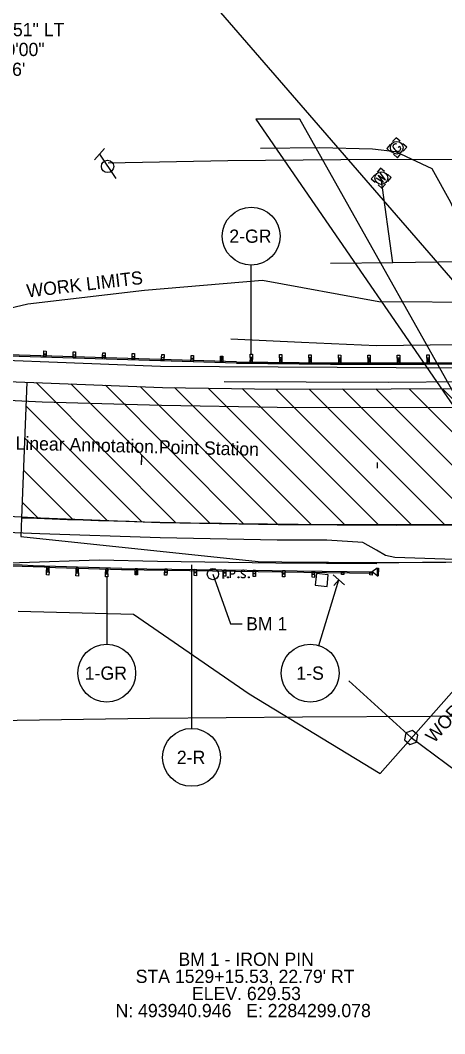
# Model space of a CAD drawing. Extents: x 0 to 1424, y 0 to 866.
# Drawn here: x 892.6 to 982.6, y 543.7 to 758.3 of the extents above; entities that cross this region are included whole.
import ezdxf

# ---------------------------------------------------------------- set-up
doc = ezdxf.new("R2010")
doc.units = 0
for name, color, linetype in [('BR_X_Sub_Backwall', 7, 'Continuous'), ('DR_P_Erosion_Control', 7, 'Continuous'), ('DR_X_Culvert', 7, 'Continuous'), ('DT_P_Slope_Break_Line', 7, 'Continuous'), ('GE_P_Alignment', 7, 'Continuous'), ('GE_P_Alignment_100_Bearings', 7, 'Continuous'), ('GE_P_Alignment_100_Distances', 7, 'Continuous'), ('GE_X_Alignment', 7, 'Continuous'), ('GE_X_Alignment_100_Stations', 7, 'Continuous'), ('GE_X_Alignment_500_Stations', 7, 'Continuous'), ('HY_P_Water_Edge', 7, 'Continuous'), ('HY_X_Water_Edge', 7, 'Continuous'), ('MT_P_Cells', 7, 'Continuous'), ('MT_P_Channelizing_Line', 7, 'Continuous'), ('MT_P_Edge_Line', 7, 'Continuous'), ('MT_P_Temp_Road', 7, 'Continuous'), ('PV_P_Drive', 7, 'Continuous'), ('PV_P_EOP', 7, 'Continuous'), ('PV_P_Shoulder', 7, 'Continuous'), ('RD_P_GR_Lt', 7, 'Continuous'), ('RD_P_GR_Rt', 7, 'Continuous'), ('TX_P_1', 7, 'Continuous'), ('TX_X_1', 7, 'Continuous'), ('XS_P_Pavt_Surface', 7, 'Continuous')]:
    doc.layers.add(name, color=color, linetype=linetype)

msp = doc.modelspace()

# ---------------------------------------------------------------- linework, layer by layer
at = {"layer": 'BR_X_Sub_Backwall'}
for points in [[(824.02, 681.8), (848.55, 680.09), (872.69, 678.71), (897.23, 677.55), (922.51, 676.8), (947.05, 676.41), (971.06, 676.33), (996.17, 676.44), (1020.51, 676.86), (1045.53, 677.69), (1069.94, 678.84), (1094.68, 680.31), (1118.73, 682.11), (1143.22, 684.24), (1168.04, 686.67), (1192.24, 689.47), (1216.36, 692.42)], [(1220.52, 668.15), (1195.56, 664.98), (1171.02, 662.21), (1146.24, 659.63), (1121.92, 657.46), (1096.96, 655.52), (1072.21, 653.97), (1047.24, 652.83), (1021.71, 652.1), (996.95, 651.5), (972.25, 651.31), (947.23, 651.51), (922.22, 651.93), (896.85, 652.91), (871.97, 654.14), (847.27, 655.73), (822.55, 657.56)]]:
    msp.add_lwpolyline(points, dxfattribs=at)
at = {"layer": 'DR_P_Erosion_Control'}
msp.add_lwpolyline([(962.21, 618.42), (975.46, 606.45), (1000.17, 588.09)], dxfattribs=at)
at = {"layer": 'DR_X_Culvert'}
for points in [[(971.56, 706.96), (969.12, 724.92)], [(1044.28, 709.35), (1023.96, 708.46), (995.75, 707.33), (971.56, 706.96), (958.36, 706.82)]]:
    msp.add_lwpolyline(points, dxfattribs=at)
at = {"layer": 'DT_P_Slope_Break_Line'}
for points in [[(911.18, 728.16), (936.61, 728.65), (960.57, 728.83), (993.7, 728.94), (1037.13, 729.19), (1044.12, 729.23), (1085.43, 729.49)], [(937.19, 690.91), (952.21, 690.16), (968.13, 689.46), (985.18, 689.67), (1004.27, 690.48), (1020.29, 691.24), (1035.82, 692.05), (1048.1, 692.21), (1057.99, 691.7), (1082.22, 691.95), (1105.42, 691.02), (1130.89, 692.35), (1156.8, 695.02)], [(935.8, 681.85), (970.56, 681.73), (1002.9, 681.96), (1019.39, 682.53), (1036.29, 683.07), (1046.18, 684.57), (1055.26, 686.21), (1082.04, 686.39), (1104.97, 686.8), (1130.94, 687.8), (1157.46, 690.58)], [(868.47, 609.78), (920.02, 610.51), (952.42, 610.79), (979.59, 610.93), (999.02, 611.08), (1014.52, 611.18), (1054.77, 611.28), (1101.52, 611.45)]]:
    msp.add_lwpolyline(points, dxfattribs=at)
at = {"layer": 'GE_P_Alignment'}
for p, q in [((893.97, 681.67), (892.85, 653)), ((895.92, 681.6), (925.52, 652)), ((903.27, 681.32), (932.74, 651.85)), ((910.62, 681.04), (939.93, 651.73)), ((917.96, 680.77), (947.09, 651.64)), ((925.25, 680.55), (954.23, 651.57)), ((932.42, 680.45), (961.34, 651.53)), ((939.59, 680.35), (968.42, 651.52)), ((946.76, 680.25), (975.48, 651.53)), ((953.83, 680.25), (982.51, 651.57)), ((960.89, 680.26), (989.52, 651.64)), ((967.96, 680.27), (993.41, 654.82)), ((975.01, 680.29), (993.32, 661.98)), ((982.06, 680.31), (993.22, 669.15)), ((893.78, 676.67), (918.27, 652.17)), ((893.51, 669.87), (911, 652.37)), ((893.24, 663.06), (903.7, 652.61)), ((892.97, 656.26), (896.37, 652.87))]:
    msp.add_line(p, q, dxfattribs=at)
at = {"layer": 'GE_P_Alignment_100_Bearings'}
for p, q in [((874.07, 830.43), (1330.4, 303.64)), ((951.83, 737.41), (942.53, 737.41)), ((941.54, 687.63), (941.54, 706.49)), ((928.89, 642.98), (928.89, 608.37)), ((910.9, 640.45), (910.9, 626.21)), ((933.41, 641.05), (937.11, 630.53)), ((955.85, 625.94), (960.13, 639.85)), ((937.11, 630.53), (939.6, 630.53))]:
    msp.add_line(p, q, dxfattribs=at)
msp.add_lwpolyline([(942.53, 737.41), (993.3, 663.68), (951.83, 737.41)], dxfattribs=at)
for centre in [(941.54, 712.62), (910.9, 620.08), (954.05, 620.08), (928.89, 602.24)]:
    msp.add_circle(centre, 6.13, dxfattribs=at)
at = {"layer": 'GE_X_Alignment'}
msp.add_line((969.12, 724.92), (969.12, 724.92), dxfattribs=at)
for points in [[(967.73, 725.61), (967, 724.78), (967.83, 724.06)], [(968, 725.01), (969.57, 724.07), (968.44, 725.51), (970.01, 724.57), (968.88, 726.01)], [(969.81, 726.31), (968.98, 727.04), (968.26, 726.21)], [(970.51, 724.23), (971.23, 725.05), (970.41, 725.78)], [(968.43, 723.53), (969.25, 722.8), (969.98, 723.63)]]:
    msp.add_lwpolyline(points, dxfattribs=at)
msp.add_circle((969.12, 724.92), 1.35, dxfattribs=at)
at = {"layer": 'GE_X_Alignment_100_Stations'}
for p, q in [((918.3, 664.17), (918.36, 666.17)), ((968.3, 663.52), (968.3, 664.72))]:
    msp.add_line(p, q, dxfattribs=at)
at = {"layer": 'GE_X_Alignment_500_Stations'}
msp.add_line((918.3, 664.17), (918.33, 665.37), dxfattribs=at)
at = {"layer": 'HY_P_Water_Edge'}
msp.add_lwpolyline([(975.16, 604.98), (976.58, 605.46), (976.88, 606.93), (975.75, 607.92), (974.33, 607.44), (974.04, 605.97), (975.16, 604.98)], dxfattribs=at)
at = {"layer": 'HY_X_Water_Edge'}
for points in [[(1057.78, 693.28), (1053.03, 689.72), (1046.91, 686.76), (1040.98, 685.3), (1034.64, 684.74), (997.19, 684.6), (922.28, 685)], [(922.28, 685), (867.59, 687.13), (831.54, 688.53)]]:
    msp.add_lwpolyline(points, dxfattribs=at)
at = {"layer": 'MT_P_Cells'}
msp.add_line((972.39, 731.35), (972.39, 731.35), dxfattribs=at)
for points in [[(971, 732.04), (970.27, 731.21), (971.1, 730.49)], [(973.08, 732.74), (972.25, 733.47), (971.52, 732.64)], [(972.33, 732.11), (972.27, 732.15), (972.19, 732.16), (972.09, 732.15), (971.96, 732.14), (971.89, 732.1), (971.84, 732.07), (971.77, 732.01), (971.66, 731.89), (971.62, 731.82), (971.61, 731.78), (971.59, 731.72), (971.58, 731.58), (971.61, 731.46), (971.66, 731.35), (971.76, 731.23), (971.91, 731.06), (972.14, 730.86), (972.33, 730.71), (972.5, 730.63), (972.69, 730.59), (972.78, 730.6), (972.88, 730.63), (973.02, 730.71), (973.12, 730.82), (973.21, 730.96), (973.22, 731.02), (973.24, 731.08), (973.23, 731.16), (973.21, 731.26), (973.15, 731.39), (972.88, 731.62), (972.69, 731.4)], [(973.78, 730.66), (974.5, 731.48), (973.68, 732.21)], [(971.7, 729.96), (972.52, 729.23), (973.25, 730.06)]]:
    msp.add_lwpolyline(points, dxfattribs=at)
msp.add_circle((972.39, 731.35), 1.35, dxfattribs=at)
at = {"layer": 'MT_P_Channelizing_Line'}
msp.add_lwpolyline([(957.87, 640.89), (955.38, 641.2), (955.06, 638.69), (957.62, 638.45)], close=True, dxfattribs=at)
at = {"layer": 'MT_P_Edge_Line'}
for points in [[(921.68, 643.69), (909.32, 643.99), (892.41, 643.44), (880.47, 643.18), (873.45, 642.75), (868.74, 641.76), (864.93, 640.06), (861.95, 637.45)], [(968.17, 643.23), (946.74, 643.39), (921.68, 643.69)]]:
    msp.add_lwpolyline(points, dxfattribs=at)
at = {"layer": 'MT_P_Temp_Road'}
for points in [[(935.43, 641.85), (935.78, 641.85)], [(935.61, 640.25), (935.61, 641.85)], [(937.17, 640.25), (937.17, 641.85), (937.7, 641.85), (937.76, 641.84), (937.83, 641.81), (937.87, 641.79), (937.9, 641.76), (937.94, 641.7), (937.98, 641.64), (938, 641.54), (938, 641.38), (937.99, 641.33), (937.97, 641.26), (937.92, 641.17), (937.88, 641.13), (937.85, 641.11), (937.79, 641.08), (937.7, 641.07), (937.17, 641.07)], [(940.18, 641.74), (940.16, 641.76), (940.13, 641.79), (940.03, 641.83), (939.91, 641.85), (939.82, 641.85), (939.79, 641.85), (939.64, 641.81), (939.52, 641.74), (939.44, 641.64), (939.42, 641.54), (939.42, 641.46), (939.44, 641.36), (939.53, 641.27), (940.14, 640.89), (940.19, 640.84), (940.22, 640.79), (940.24, 640.72), (940.24, 640.64), (940.23, 640.57), (940.22, 640.52), (940.19, 640.45), (940.17, 640.4), (940.15, 640.36), (940.12, 640.33), (940.08, 640.3), (940.04, 640.28), (940.01, 640.26), (939.91, 640.25), (939.75, 640.25), (939.65, 640.28), (939.51, 640.36), (939.42, 640.44)], [(935.43, 640.25), (935.78, 640.25)], [(936.57, 640.47), (936.62, 640.47), (936.66, 640.44), (936.69, 640.39), (936.69, 640.33), (936.66, 640.28), (936.62, 640.25), (936.57, 640.25), (936.53, 640.28), (936.5, 640.33), (936.5, 640.39), (936.53, 640.44), (936.57, 640.47)], [(938.82, 640.47), (938.87, 640.47), (938.9, 640.44), (938.94, 640.39), (938.94, 640.33), (938.9, 640.28), (938.87, 640.25), (938.82, 640.25), (938.78, 640.28), (938.75, 640.33), (938.75, 640.39), (938.78, 640.44), (938.82, 640.47)], [(941, 640.47), (941.05, 640.47), (941.09, 640.44), (941.12, 640.39), (941.12, 640.33), (941.09, 640.28), (941.05, 640.25), (941, 640.25), (940.97, 640.28), (940.93, 640.33), (940.93, 640.39), (940.97, 640.44), (941, 640.47)]]:
    msp.add_lwpolyline(points, dxfattribs=at)
msp.add_circle((933.41, 641.05), 1.2, dxfattribs=at)
at = {"layer": 'PV_P_Drive'}
msp.add_lwpolyline([(943.54, 731.24), (956.01, 731.4), (967.27, 731.12), (972.12, 730.53), (979.8, 726.97), (983.81, 719.8), (987.99, 710.05), (990.77, 698.45), (992.8, 689.85), (995.65, 680.91), (1004.63, 650.62), (1011.63, 633.87), (1017.52, 622.44), (1021.49, 613.78), (1027.14, 601.74), (1033.23, 579.15), (1036.77, 573.22), (1038.45, 568.65), (1049.99, 569.23), (1061.67, 569.6), (1072.89, 570.06), (1092.92, 570.52), (1114.64, 572.62)], dxfattribs=at)
at = {"layer": 'PV_P_EOP'}
msp.add_arc((968.3, 2573.38), 1921.86, 267.75, 273.96964, dxfattribs=at)
at = {"layer": 'PV_P_Shoulder'}
for p, q in [((892.85, 653), (892.69, 649.01)), ((892.69, 649.01), (943.04, 643.69))]:
    msp.add_line(p, q, dxfattribs=at)
msp.add_arc((968.3, 2573.38), 1929.86, 269.25, 273.96964, dxfattribs=at)
at = {"layer": 'RD_P_GR_Lt'}
for p, q in [((938.39, 685.76), (885.28, 687.35)), ((938.39, 686.01), (885.29, 687.6)), ((898.07, 688.3), (898.03, 686.97)), ((904.32, 688.11), (904.28, 686.78)), ((910.56, 687.93), (910.52, 686.59)), ((916.81, 687.74), (916.77, 686.4)), ((923.06, 687.55), (923.02, 686.22)), ((929.3, 687.37), (929.26, 686.03)), ((935.26, 685.85), (935.3, 687.19)), ((935.55, 687.18), (935.51, 685.84)), ((941.28, 686.96), (941.26, 685.96)), ((941.78, 686.96), (941.26, 685.96)), ((941.28, 686.96), (941.76, 685.96)), ((941.78, 686.96), (941.76, 685.96)), ((947.52, 686.88), (947.51, 685.88)), ((948.02, 686.88), (947.51, 685.88)), ((947.52, 686.88), (948.01, 685.88)), ((948.02, 686.88), (948.01, 685.88)), ((941.26, 685.96), (941.76, 685.96)), ((947.51, 685.88), (948.01, 685.88)), ((953.77, 686.83), (953.76, 685.83)), ((954.27, 686.82), (953.76, 685.83)), ((953.76, 685.83), (954.26, 685.82)), ((953.77, 686.83), (954.26, 685.82)), ((954.27, 686.82), (954.26, 685.82)), ((960.02, 686.79), (960.01, 685.79)), ((960.52, 686.79), (960.01, 685.79)), ((960.01, 685.79), (960.51, 685.79)), ((960.02, 686.79), (960.51, 685.79)), ((960.52, 686.79), (960.51, 685.79)), ((966.26, 686.77), (966.26, 685.77)), ((966.26, 686.77), (966.76, 685.77)), ((966.76, 686.77), (966.26, 685.77)), ((966.26, 685.77), (966.76, 685.77)), ((966.76, 686.77), (966.76, 685.77)), ((972.51, 686.78), (972.51, 685.78)), ((972.51, 686.78), (973.01, 685.78)), ((973.01, 686.78), (972.51, 685.78)), ((972.51, 685.78), (973.01, 685.78)), ((973.01, 686.78), (973.01, 685.78)), ((978.75, 686.8), (978.76, 685.8)), ((978.75, 686.8), (979.26, 685.8)), ((979.25, 686.8), (978.76, 685.8)), ((978.76, 685.8), (979.26, 685.8)), ((979.25, 686.8), (979.26, 685.8))]:
    msp.add_line(p, q, dxfattribs=at)
for points in [[(898.03, 686.97), (897.53, 686.98), (897.55, 687.65), (898.05, 687.63)], [(898.05, 687.63), (897.55, 687.65), (897.57, 688.32), (898.07, 688.3)], [(904.28, 686.78), (903.78, 686.79), (903.8, 687.46), (904.3, 687.45)], [(904.3, 687.45), (903.8, 687.46), (903.82, 688.13), (904.32, 688.11)], [(910.52, 686.59), (910.02, 686.61), (910.04, 687.27), (910.54, 687.26)], [(910.54, 687.26), (910.04, 687.27), (910.06, 687.94), (910.56, 687.93)], [(916.77, 686.4), (916.27, 686.42), (916.29, 687.09), (916.79, 687.07)], [(916.79, 687.07), (916.29, 687.09), (916.31, 687.75), (916.81, 687.74)], [(923.02, 686.22), (922.52, 686.23), (922.54, 686.9), (923.04, 686.88)], [(923.04, 686.88), (922.54, 686.9), (922.56, 687.57), (923.06, 687.55)], [(929.28, 686.7), (928.79, 686.71), (928.81, 687.38), (929.3, 687.37)], [(935.53, 686.51), (935.03, 686.53), (935.05, 687.19), (935.55, 687.18)], [(941.78, 686.96), (941.28, 686.96), (941.29, 687.63), (941.79, 687.62)], [(948.02, 686.88), (947.52, 686.88), (947.53, 687.55), (948.03, 687.55)], [(954.27, 686.82), (953.77, 686.83), (953.77, 687.49), (954.27, 687.49)], [(960.52, 686.79), (960.02, 686.79), (960.02, 687.46), (960.52, 687.45)], [(966.76, 686.77), (966.26, 686.77), (966.26, 687.44), (966.76, 687.44)], [(973.01, 686.78), (972.51, 686.78), (972.51, 687.44), (973.01, 687.44)], [(979.25, 686.8), (978.75, 686.8), (978.75, 687.47), (979.25, 687.47)], [(929.26, 686.03), (928.77, 686.05), (928.79, 686.71), (929.28, 686.7)], [(935.51, 685.84), (935.01, 685.86), (935.03, 686.53), (935.53, 686.51)]]:
    msp.add_lwpolyline(points, close=True, dxfattribs=at)
for radius, start in [(1887.61, 269.09215), (1887.86, 269.09217)]:
    msp.add_arc((968.3, 2573.38), radius, start, 272.31694, dxfattribs=at)
at = {"layer": 'RD_P_GR_Rt'}
for p, q in [((910.43, 731.19), (908.32, 728.79)), ((909.38, 729.99), (912.82, 724.82)), ((898.17, 641.54), (898.2, 642.54)), ((898.17, 641.54), (898.7, 642.52)), ((898.7, 642.52), (898.2, 642.54)), ((898.67, 641.52), (898.2, 642.54)), ((898.67, 641.52), (898.7, 642.52)), ((904.42, 641.32), (904.45, 642.32)), ((904.42, 641.32), (904.95, 642.3)), ((904.95, 642.3), (904.45, 642.32)), ((904.92, 641.3), (904.45, 642.32)), ((904.92, 641.3), (904.95, 642.3)), ((910.67, 641.12), (910.7, 642.12)), ((910.67, 641.12), (911.2, 642.11)), ((911.2, 642.11), (910.7, 642.12)), ((911.17, 641.11), (910.7, 642.12)), ((911.17, 641.11), (911.2, 642.11)), ((914.07, 642.02), (967.19, 641.27)), ((914.08, 642.27), (967.2, 641.52)), ((916.94, 640.9), (916.95, 642.23)), ((917.2, 642.23), (917.18, 640.89)), ((923.18, 640.81), (923.2, 642.15)), ((929.43, 640.72), (929.45, 642.06)), ((935.68, 640.63), (935.7, 641.97)), ((941.93, 640.54), (941.95, 641.88)), ((968.24, 642.34), (967.2, 641.52)), ((968.24, 642.34), (968.22, 640.67)), ((968.24, 642.34), (968.49, 642.34)), ((968.29, 642.34), (968.27, 640.67)), ((968.49, 642.34), (968.47, 640.67)), ((948.18, 640.45), (948.2, 641.79)), ((954.43, 640.37), (954.45, 641.7)), ((968.22, 640.67), (967.2, 641.52)), ((968.22, 640.67), (968.47, 640.67))]:
    msp.add_line(p, q, dxfattribs=at)
for points in [[(916.95, 642.23), (917.45, 642.23), (917.44, 641.56), (916.94, 641.57)], [(923.2, 642.15), (923.7, 642.14), (923.69, 641.47), (923.19, 641.48)], [(929.45, 642.06), (929.95, 642.05), (929.94, 641.38), (929.44, 641.39)], [(935.7, 641.97), (936.2, 641.96), (936.19, 641.29), (935.69, 641.3)], [(941.95, 641.88), (942.45, 641.87), (942.44, 641.2), (941.94, 641.21)], [(898.17, 641.54), (898.67, 641.52), (898.64, 640.85), (898.14, 640.87)], [(904.42, 641.32), (904.92, 641.3), (904.89, 640.64), (904.39, 640.65)], [(910.67, 641.12), (911.17, 641.11), (911.15, 640.44), (910.65, 640.46)], [(916.94, 641.57), (917.44, 641.56), (917.43, 640.89), (916.94, 640.9)], [(923.19, 641.48), (923.69, 641.47), (923.68, 640.8), (923.18, 640.81)], [(929.44, 641.39), (929.94, 641.38), (929.93, 640.71), (929.43, 640.72)], [(935.69, 641.3), (936.19, 641.29), (936.18, 640.63), (935.68, 640.63)], [(941.94, 641.21), (942.44, 641.2), (942.43, 640.54), (941.93, 640.54)], [(948.19, 641.12), (948.69, 641.12), (948.68, 640.45), (948.18, 640.45)], [(948.2, 641.79), (948.7, 641.78), (948.69, 641.12), (948.19, 641.12)], [(954.44, 641.03), (954.94, 641.03), (954.93, 640.36), (954.43, 640.37)], [(954.45, 641.7), (954.95, 641.69), (954.94, 641.03), (954.44, 641.03)], [(960.7, 641.61), (961.2, 641.61), (961.19, 640.94), (960.69, 640.95)], [(966.7, 641.53), (967.2, 641.52), (967.19, 640.85), (966.69, 640.86)]]:
    msp.add_lwpolyline(points, close=True, dxfattribs=at)
msp.add_circle((911.1, 727.41), 1.3, dxfattribs=at)
for radius, start in [(1932.11, 267.27958), (1931.86, 267.27957)]:
    msp.add_arc((968.3, 2573.38), radius, start, 268.39176, dxfattribs=at)
at = {"layer": 'TX_P_1'}
for points in [[(824.45, 685.38), (848.71, 683.65), (872.94, 682.49), (897.31, 681.54), (922.75, 680.59), (947.11, 680.25), (971.2, 680.27), (996.18, 680.35), (1020.4, 680.63), (1045.46, 681.64), (1069.73, 682.81), (1080.26, 683.8), (1094.6, 683.9), (1108.74, 685.27), (1112.46, 686.53), (1118.53, 686.7), (1125.87, 687.13), (1129.02, 686.38), (1143.02, 687.32), (1167.77, 689.75), (1191.96, 692.49), (1216.02, 695.75)], [(984.72, 644.14), (972.01, 644.6), (970.02, 645.01), (968.11, 646.1), (965.2, 647.71), (957.59, 648.22), (947.06, 648.27), (922.21, 648.7), (896.72, 649.56), (871.84, 650.59)]]:
    msp.add_lwpolyline(points, dxfattribs=at)
at = {"layer": 'TX_X_1'}
for points in [[(991.24, 698.56), (968.58, 698.75), (943.92, 703.2), (918.89, 701.13), (894.15, 698.22)], [(894.15, 698.22), (865.93, 691.59), (820.24, 692.12), (817.13, 652.67), (847.35, 645.73)], [(892.1, 633.22), (916.58, 632.54), (941.07, 615.69), (968.88, 598.84)], [(968.88, 598.84), (995.33, 628.65), (1017.04, 633.64)]]:
    msp.add_lwpolyline(points, dxfattribs=at)
at = {"layer": 'XS_P_Pavt_Surface'}
for p, q in [((958.93, 640.9), (961.33, 638.79)), ((960.13, 639.85), (959.07, 638.65))]:
    msp.add_line(p, q, dxfattribs=at)

# ---------------------------------------------------------------- texts
at = {"layer": 'GE_P_Alignment_100_Bearings'}
for s, p in [('2-GR', (936.89, 711.22)), ('BM 1', (940.45, 629.13)), ('1-GR', (906.25, 618.68)), ('1-S', (951.11, 618.68)), ('2-R', (925.77, 600.84)), ('BM 1 - IRON PIN', (926.11, 558.08)), ("STA 1529+15.53, 22.79' RT", (917.04, 554.46)), ('ELEV. 629.53', (928.97, 550.83)), ('N: 493940.946   E: 2284299.078', (912.77, 547.21))]:
    msp.add_text(s, height=2.8, dxfattribs=at).set_placement(p)
for rotation, p in [(6.7083, (894.1, 699.62)), (48.4222, (980.29, 605.1))]:
    msp.add_text('WORK LIMITS', height=2.8, rotation=rotation, dxfattribs=at).set_placement(p)
at = {"layer": 'GE_P_Alignment_100_Distances'}
for s, p in [('25°26\'51" LT', (880.48, 754.97)), ('03°00\'00"', (881.7, 750.77)), ("R  = 1909.86'", (871.38, 746.57))]:
    msp.add_text(s, height=2.8, dxfattribs=at).set_placement(p)
at = {"layer": 'GE_X_Alignment_100_Stations'}
msp.add_text('Linear Annotation.Point Station', height=2.8, rotation=358.5, dxfattribs=at).set_placement((891.54, 667.42))

doc.saveas('drawing.dxf')
